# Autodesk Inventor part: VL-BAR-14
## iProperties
Created: 2005-08
Part Number: VL-BAR-14
Document SubType Name: Sheet Metal
Density: 1 g/cm^3
Mass: 2.36703 g
Surface Area: 45.8308 cm^2
Volume: 2.36703 cm^3
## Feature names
1. Rectangular Pattern1
2. Plate1
